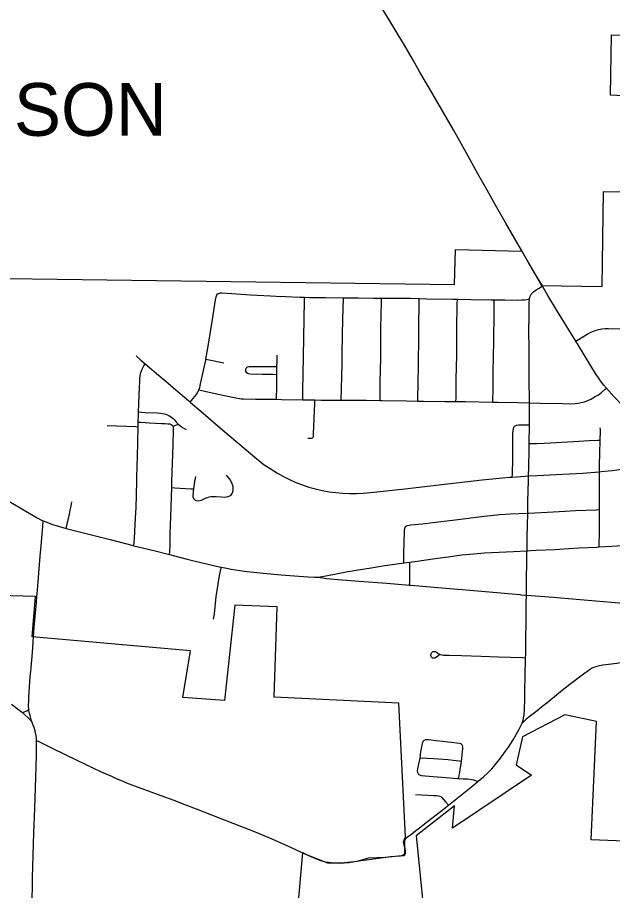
# Model space of a CAD drawing. Extents: x 1815539 to 1947826, y 273303 to 993194.
# Drawn here: x 1869978 to 1875617, y 925558 to 933838 of the extents above; entities that cross this region are included whole.
import ezdxf

# ---------------------------------------------------------------- set-up
doc = ezdxf.new("R2010")
doc.units = 0
for name, color, linetype in [('GM_X_City_Street', 7, 'Continuous'), ('GM_X_Corporation', 7, 'Continuous'), ('GM_X_Corporation_Text', 7, 'Continuous'), ('GM_X_County_Road', 7, 'Continuous'), ('GM_X_State_Route', 7, 'Continuous'), ('GM_X_Township_Road', 7, 'Continuous')]:
    doc.layers.add(name, color=color, linetype=linetype)

msp = doc.modelspace()

# ---------------------------------------------------------------- linework, layer by layer
at = {"layer": 'GM_X_City_Street'}
for points in [[(1874829, 931170.4), (1874832.1, 931185.5), (1874838, 931199.5), (1874846.5, 931212.7), (1874856.7, 931224.6), (1874868.3, 931235.4), (1874893.7, 931255.1), (1874920.8, 931272.3), (1874951.7, 931292)], [(1875268.5, 930769.3), (1875243.4, 930810.5), (1875096.9, 931048.5), (1875003.8, 931203.1), (1874953.7, 931288.6), (1874951.7, 931292)], [(1871763.6, 930597.2), (1871782.7, 930701.2), (1871825.7, 930973.5), (1871855.1, 931161.2), (1871860.9, 931189.5), (1871863.5, 931197.1), (1871868.1, 931207.8), (1871873.8, 931216.9)], [(1871873.8, 931216.9), (1871883.5, 931221.8), (1871891.7, 931224.8), (1871903.1, 931226.6), (1871915.8, 931226.3), (1871965.5, 931224.1), (1872184.9, 931209.3), (1872374.5, 931197.1), (1872430.9, 931193.7), (1872518.8, 931190.8), (1872655.1, 931186.4), (1872698.3, 931185.3)], [(1872681.8, 930213.3), (1872682, 930232.4), (1872682.7, 930308.9), (1872684.2, 930451.6), (1872697.6, 931150.5), (1872698.3, 931185.3)], [(1872698.3, 931185.3), (1872745, 931184.1), (1872898.3, 931181.7), (1873067.2, 931178.4)], [(1873045.4, 930208.6), (1873048.7, 930318.4), (1873053.4, 930546.7), (1873054.8, 930644.7), (1873059.3, 930829.7), (1873062.2, 930973.8), (1873067.2, 931178.4)], [(1873067.2, 931178.4), (1873207, 931178.5), (1873351.1, 931177), (1873427.8, 931176.4)], [(1873414.1, 930206.3), (1873414.4, 930230.8), (1873415.5, 930329.2), (1873416.5, 930395), (1873417.8, 930477.2), (1873420, 930624.9), (1873421.3, 930723.5), (1873422.3, 930871.6), (1873424.9, 931035.8), (1873427.3, 931117.9), (1873427.7, 931165.5), (1873427.8, 931176.4)], [(1873427.8, 931176.4), (1873503.4, 931175.6), (1873702.3, 931174.9), (1873785.5, 931173)], [(1873773.1, 930200.7), (1873773.3, 930219.9), (1873774.8, 930371.2), (1873777, 930533.7), (1873778.4, 930632.9), (1873779.9, 930728), (1873781.4, 930851.3), (1873782.1, 930972.7), (1873783.6, 931060.8), (1873785, 931146.2), (1873785.5, 931173)], [(1873785.5, 931173), (1873857.3, 931171.4), (1874103.6, 931166.4), (1874146.4, 931165.9)], [(1874133.2, 930195.9), (1874133.8, 930229.1), (1874136.4, 930392.3), (1874138.6, 930539.2), (1874140, 930620.8), (1874140.7, 930767.6), (1874141.2, 930881.9), (1874145.7, 931122.2), (1874146.4, 931165.9)], [(1874146.4, 931165.9), (1874276.6, 931164.2), (1874465.6, 931161.3), (1874496.8, 931160.9)], [(1874483.8, 930191.4), (1874483.9, 930218.4), (1874484.3, 930301.1), (1874487, 930416.8), (1874487.1, 930482.9), (1874488.9, 930615.1), (1874491.3, 930780.3), (1874491.9, 930846.3), (1874495.3, 930953.9), (1874496.2, 931044.8), (1874496.7, 931144.1), (1874496.8, 931160.9)], [(1874496.8, 931160.9), (1874597.2, 931159.8), (1874718.1, 931158.3), (1874757.8, 931159.1), (1874783.4, 931161.5), (1874805.1, 931164.8), (1874829, 931170.4)], [(1874829.6, 930184.1), (1874829.4, 930208.1), (1874828.9, 930257.2), (1874827.8, 930355.1), (1874827.4, 930432.6), (1874826.8, 930502), (1874826.2, 930583.6), (1874825.6, 930703.9), (1874825, 930860.9), (1874826.5, 931007.8), (1874826.9, 931138.3), (1874829, 931170.4)], [(1875268.5, 930769.3), (1875294, 930784.8), (1875336, 930810.4), (1875392.7, 930842.9), (1875421.8, 930857.1), (1875451.9, 930869), (1875483, 930878.3), (1875514.6, 930884.9), (1875546.6, 930888.1), (1875579.2, 930888.5), (1875710.2, 930884.3), (1875778.4, 930881.9)], [(1875559.9, 930322.9), (1875533.8, 930352.1), (1875503, 930391), (1875483.3, 930419.4), (1875461.6, 930453.1), (1875431.4, 930501.6), (1875328.7, 930670.1), (1875268.5, 930769.3)], [(1871101.6, 930629.6), (1871148.3, 930589.1), (1871189.5, 930553.2)], [(1872436.7, 930527.2), (1872437.4, 930570), (1872440.4, 930634.6)], [(1871125.7, 930097.1), (1871125.8, 930103.8), (1871128, 930171.6), (1871129.4, 930202.4), (1871130.5, 930230), (1871131.1, 930245.9), (1871131.2, 930259.4), (1871134.1, 930324.7), (1871136.6, 930390.4), (1871139, 930418.8), (1871141.2, 930438.7), (1871143.6, 930455.2), (1871147.6, 930471), (1871152.5, 930487.3), (1871158.2, 930502), (1871164.6, 930515.1), (1871175, 930533.3), (1871189.5, 930553.2)], [(1871189.5, 930553.2), (1871229.7, 930519.4), (1871295.7, 930462.9), (1871383.1, 930388.2), (1871478, 930307.1), (1871600.7, 930201.6), (1871615.3, 930189)], [(1871696.2, 930306), (1871704.9, 930328.7), (1871713.6, 930363.8), (1871762, 930588.1), (1871763.6, 930597.2)], [(1871763.6, 930597.2), (1871793.3, 930590.8), (1871932, 930561.4)], [(1872435.9, 930449.4), (1872396.4, 930451.5), (1872363.5, 930453.3), (1872297.4, 930453.8), (1872181.8, 930456.3), (1872165.5, 930459.2), (1872151.4, 930467.5), (1872143, 930481.3), (1872141.7, 930497.7), (1872146.4, 930513.7), (1872157.5, 930525.3), (1872173.4, 930529.3), (1872271, 930526.9), (1872403.2, 930527.1), (1872436.7, 930527.2)], [(1872435.9, 930449.4), (1872436, 930489.1), (1872436.7, 930527.2)], [(1872432, 930216.9), (1872433, 930246.5), (1872435.3, 930311.2), (1872435.9, 930449.4)], [(1871615.3, 930189), (1871640.9, 930222), (1871660.4, 930247.1), (1871683, 930279.9), (1871694.1, 930300.6), (1871696.2, 930306)], [(1871696.2, 930306), (1871726.4, 930299.6), (1871752.1, 930294.1), (1871881.4, 930266.4), (1872031.6, 930233.8), (1872096.3, 930222.6), (1872120.6, 930220.6), (1872233.2, 930218), (1872432, 930216.9)], [(1874829.6, 930184.1), (1874934.6, 930181.8), (1875148.4, 930176.9), (1875216.8, 930175.6), (1875263.6, 930176.4), (1875292.4, 930180.3), (1875320.8, 930185.6), (1875351.9, 930194.5), (1875382, 930205.9), (1875411.2, 930219.5), (1875453.1, 930242.1), (1875483.5, 930260.5), (1875512.4, 930281.4), (1875544.3, 930309.3), (1875559.9, 930322.9)], [(1875898.3, 929941.1), (1875888.8, 929955), (1875873.9, 929973.2), (1875852.7, 929998.3), (1875820.1, 930035.2), (1875710.5, 930157.2), (1875632.4, 930241.6), (1875559.9, 930322.9)], [(1872432, 930216.9), (1872479.5, 930216.7), (1872681.8, 930213.3)], [(1872681.8, 930213.3), (1872709.4, 930212.8), (1872796.8, 930210.9)], [(1872730.1, 929849.5), (1872765.1, 929849.3), (1872772.5, 929850.6), (1872778, 929854), (1872780.8, 929859.3), (1872782.9, 929865.7), (1872783.8, 929872), (1872784.5, 929887.5), (1872786.6, 929966.1), (1872792.2, 930099.9), (1872795.6, 930181.9), (1872796.8, 930210.9)], [(1872796.8, 930210.9), (1872857.2, 930209.5), (1873045.4, 930208.6)], [(1873045.4, 930208.6), (1873139.8, 930209.3), (1873287, 930208.1), (1873414.1, 930206.3)], [(1871615.3, 930189), (1871619, 930185.9), (1871714.6, 930103.8), (1871902.5, 929944.4), (1872064.7, 929805.8), (1872265.7, 929637), (1872317.3, 929597), (1872371.2, 929559.9), (1872440.8, 929517), (1872498.2, 929485.4), (1872556.7, 929456.1), (1872616.5, 929429.4), (1872677.5, 929405.7), (1872739.5, 929385), (1872802.4, 929366.9), (1872866.1, 929351.8), (1872930.4, 929340.1), (1872995.3, 929331.7), (1873060.6, 929326.1), (1873125.9, 929323.2), (1873190.9, 929323.3), (1873256, 929326.4), (1873353.7, 929335.4), (1873647.5, 929367.3), (1874136.7, 929423.6), (1874381.3, 929452.9), (1874511.9, 929466.9), (1874643, 929477.6), (1874667.1, 929479.3)], [(1873414.1, 930206.3), (1873434.2, 930206.1), (1873663.1, 930203), (1873773.1, 930200.7)], [(1873773.1, 930200.7), (1873826.7, 930199.6), (1874027.1, 930197.1), (1874133.2, 930195.9)], [(1874133.2, 930195.9), (1874219.3, 930195), (1874483.8, 930191.4)], [(1874483.8, 930191.4), (1874528.9, 930190.8), (1874718.7, 930186.5), (1874829.6, 930184.1)], [(1874829.6, 929973.9), (1874830.4, 930077.6), (1874829.6, 930184.1)], [(1871122.9, 930000.1), (1871124.9, 930070.3), (1871125.7, 930097.1)], [(1871125.7, 930097.1), (1871154.5, 930095.4), (1871187.1, 930093.5), (1871301.9, 930088.4), (1871334.5, 930085.2), (1871366.9, 930079.2), (1871382.7, 930075), (1871398, 930069.1), (1871412.9, 930062.2), (1871427, 930053.8), (1871440.3, 930044.1), (1871452.9, 930033.6), (1871464.6, 930022.2), (1871485.3, 929996.8), (1871496.7, 929985), (1871503.8, 929978.7)], [(1870828.7, 929967.4), (1871097.5, 929957.7), (1871121.7, 929956.8)], [(1871121.7, 929956.8), (1871122.9, 930000.1)], [(1871122.9, 930000.1), (1871148.5, 929998.7), (1871228.7, 929994.1), (1871343.8, 929988.4), (1871376.1, 929987.1), (1871403.4, 929985.2), (1871422.2, 929982.9), (1871433.8, 929979), (1871444.9, 929973.3), (1871458, 929963.7)], [(1871440.4, 929380.4), (1871442, 929432.1), (1871444.4, 929529.9), (1871449.8, 929692.7), (1871452.2, 929790.3), (1871456.4, 929925.1), (1871458, 929963.7)], [(1871458, 929963.7), (1871486.3, 929973.5), (1871503.8, 929978.7)], [(1871503.8, 929978.7), (1871509, 929974.1), (1871524.8, 929961.8), (1871543.2, 929949.1), (1871562.9, 929937.2), (1871577.8, 929929.5)], [(1874667.1, 929479.3), (1874667.7, 929507.2), (1874671.2, 929655.9), (1874671.1, 929753.9), (1874671.7, 929886.6), (1874674, 929919.8), (1874677.1, 929936.1), (1874682.5, 929951.8), (1874693.3, 929964.2), (1874708.2, 929971.1), (1874724.6, 929974.2), (1874741.2, 929975), (1874774.5, 929975.2), (1874829.6, 929973.9)], [(1874828.1, 929796.8), (1874829.6, 929973.9)], [(1871081.7, 928828.8), (1871084.4, 928865), (1871086.8, 928897.5), (1871090.8, 928962.7), (1871097.5, 929092.9), (1871099.5, 929141.8), (1871101.4, 929190.6), (1871105.5, 929303.4), (1871106, 929335.2), (1871106.7, 929351.3), (1871108.1, 929399), (1871108.9, 929431.6), (1871109.3, 929449.8), (1871109.9, 929473.2), (1871110.7, 929503.6), (1871111.9, 929555), (1871116.5, 929714.1), (1871117.6, 929770.2), (1871118.5, 929811), (1871119.5, 929863.1), (1871120.3, 929903), (1871120.7, 929923.5), (1871121.7, 929956.8)], [(1875500, 929830.8), (1875502.7, 929914.1), (1875502.4, 929930.4), (1875500.8, 929946.8)], [(1874821.4, 929489.8), (1874823.5, 929575.5), (1874827.5, 929739), (1874828.1, 929796.8)], [(1874828.1, 929796.8), (1874853.3, 929797.3), (1874902.6, 929798.3), (1874968.1, 929801.7), (1875033.5, 929805), (1875131.9, 929809.2), (1875246.7, 929816.1), (1875394.4, 929824.9), (1875476, 929829.5), (1875500, 929830.8)], [(1875494.8, 929529.6), (1875494.6, 929586.3), (1875496.8, 929717.3), (1875499.5, 929815.6), (1875500, 929830.8)], [(1875494.8, 929529.6), (1875509.6, 929530.9), (1875574.3, 929537.9), (1875615.7, 929543.3), (1875659.1, 929549.3), (1875742.5, 929561.5), (1875849.6, 929577.5), (1876028.5, 929599.5), (1876058, 929603.1)], [(1871646.8, 929366.5), (1871639.8, 929307.8), (1871641, 929291.5), (1871647.1, 929276.4), (1871657.9, 929264.3), (1871672.4, 929257.1), (1871688.5, 929255.1), (1871704.9, 929256.8), (1871720.8, 929261), (1871736, 929267.1), (1871765.1, 929281.9), (1871780.2, 929287.2), (1871796, 929291.6), (1871812, 929294.6), (1871828.2, 929296.2), (1871844.6, 929296.7), (1871861, 929296), (1871909.8, 929291.5), (1871942.5, 929289.4), (1871958.9, 929290.6), (1871974.6, 929294.5), (1871989.1, 929301.8), (1872001.5, 929312.2), (1872011.3, 929325.3), (1872018.3, 929340.2), (1872022.3, 929356), (1872023.3, 929372.3), (1872021.3, 929388.6), (1872017.1, 929404.4), (1872011.2, 929419.7), (1872004.2, 929434.4), (1871996.2, 929448.7), (1871987, 929462.2), (1871957.5, 929499)], [(1871664.8, 929485.4), (1871655.8, 929437.1), (1871649.5, 929389.3), (1871646.8, 929366.5)], [(1874667.1, 929479.3), (1874787.6, 929487.6), (1874821.4, 929489.8)], [(1874812.7, 929138.2), (1874814.5, 929232.2), (1874818.2, 929362.9), (1874820, 929428.3), (1874821.4, 929489.8)], [(1874821.4, 929489.8), (1874904.1, 929495.6), (1875084.3, 929504.2), (1875211.1, 929511.2), (1875335.3, 929518), (1875411.7, 929522.3), (1875494.8, 929529.6)], [(1875493.4, 929171.8), (1875494.3, 929323.8), (1875494.9, 929455.1), (1875494.8, 929529.6)], [(1871419.3, 928744.5), (1871420.6, 928770), (1871423.8, 928834), (1871425.8, 928943.2), (1871431.9, 929106.2), (1871440.4, 929380.4)], [(1871440.4, 929380.4), (1871468.3, 929378.3), (1871519.8, 929374.4), (1871623.1, 929368), (1871646.8, 929366.5)], [(1870440.9, 928992.5), (1870446.9, 929019.7), (1870470.9, 929126.9), (1870479, 929165.4), (1870486.8, 929204.4), (1870492.9, 929243.4)], [(1873655.7, 929010.9), (1873664.2, 929017.5), (1873672.4, 929021.3), (1873688.8, 929024.6), (1873705.8, 929026.1), (1873816.2, 929037.1), (1873913.5, 929048.5), (1874124.8, 929073.2), (1874401, 929107.3), (1874547.4, 929123.5), (1874645.3, 929130.6), (1874812.7, 929138.2)], [(1874806.6, 928780.7), (1874808.3, 928906.2), (1874812.7, 929138.2)], [(1874812.7, 929138.2), (1874825.1, 929138.5), (1875053.9, 929150.6), (1875168.4, 929156.5), (1875266.4, 929161.7), (1875462.3, 929170.4), (1875493.4, 929171.8)], [(1875491.2, 928817.1), (1875491.5, 928851.4), (1875491.7, 928878.3), (1875491.9, 928912.2), (1875492.1, 928942.5), (1875492.7, 929041.5), (1875493.5, 929144), (1875493.4, 929171.8)], [(1870163, 928351.1), (1870164.5, 928371.7), (1870174.4, 928485.2), (1870193, 928728.9), (1870202, 928827.7), (1870211.5, 928938.9), (1870217.7, 929011.7), (1870221.9, 929063.9)], [(1873640.8, 928664.7), (1873640.6, 928694.5), (1873640.4, 928742.8), (1873641.6, 928871.8), (1873644.2, 928961.1), (1873645.2, 928969), (1873646.1, 928981.1), (1873647.5, 928991.1), (1873650.6, 929001.3), (1873655.7, 929010.9)], [(1874800.2, 928360), (1874801.3, 928452), (1874802.5, 928550.1), (1874803.8, 928635.5), (1874806.1, 928756.3), (1874806.6, 928780.7)], [(1873693.1, 928455.9), (1873695.4, 928483.5), (1873696.7, 928499), (1873696.6, 928545.7), (1873696.5, 928639.2), (1873696.5, 928672.6)], [(1871837.2, 928133), (1871844.2, 928182), (1871862.5, 928345.8), (1871873, 928427.4), (1871886.5, 928508.7), (1871900.4, 928575.6), (1871908.3, 928614.6), (1871910.4, 928625.1)], [(1874792.8, 927766), (1874793.8, 927796.7), (1874795.3, 927944.3), (1874797.2, 928108.1), (1874798.4, 928196.7), (1874799.2, 928281.7), (1874800.2, 928360)], [(1873981.2, 927795.9), (1873957, 927776.8), (1873943.8, 927768.3), (1873933.7, 927763.3), (1873923.9, 927761.7), (1873915.5, 927763.1), (1873908.8, 927766), (1873902.5, 927771.7), (1873898.2, 927778), (1873896.1, 927785.9), (1873895.5, 927793.8), (1873897, 927802.1), (1873899.9, 927809.4), (1873905.6, 927816.5), (1873911.3, 927820.9), (1873918.7, 927824.2), (1873926.6, 927825.2), (1873936, 927824.2), (1873942.3, 927821.2), (1873949.9, 927817.6), (1873956.6, 927813.1), (1873969.9, 927803.8), (1873984.6, 927796.8), (1873999.4, 927793.3), (1874015.1, 927791.5), (1874068.2, 927789.4), (1874184.1, 927786.5), (1874373.5, 927781.4), (1874536.2, 927774.9), (1874764.3, 927767), (1874792.8, 927766)], [(1874782.6, 927269.5), (1874783.9, 927309.6), (1874785.1, 927338.1), (1874787.3, 927465.6), (1874788.3, 927583.9), (1874792.8, 927766)], [(1874901.3, 927266.1), (1874943.3, 927299.4), (1874960.1, 927312.9), (1874981.5, 927330.1), (1875008.8, 927352.1), (1875035.1, 927373.1), (1875047.7, 927383.3), (1875123.9, 927444.5), (1875213.7, 927514.2), (1875343.1, 927614.1), (1875382.3, 927642.9), (1875398.9, 927654.5), (1875418.9, 927666.7), (1875438.2, 927675.1), (1875452.9, 927681), (1875471, 927686.7), (1875493.6, 927692.7), (1875523.9, 927697.9), (1875606.7, 927708.8), (1875677.1, 927718.1), (1875741.8, 927725.5), (1875823.1, 927733.8)], [(1874761.8, 927145.5), (1874769.1, 927173.2), (1874774.3, 927196.8), (1874779.1, 927229), (1874782.6, 927269.5)], [(1874761.8, 927145.5), (1874788, 927174.8), (1874806.5, 927192), (1874825.1, 927206.5), (1874852, 927227.6), (1874877.9, 927247.8), (1874901.3, 927266.1)], [(1874339, 926592.6), (1874365.4, 926612.9), (1874390.3, 926634), (1874437.9, 926678.7), (1874472, 926713.8), (1874504.2, 926750.5), (1874555.3, 926813.8), (1874603.8, 926879.1), (1874631.1, 926919.5), (1874674.1, 926988.6), (1874730.6, 927087.2), (1874761.8, 927145.5)], [(1874184.7, 926783.9), (1874187.9, 926806.2), (1874196.5, 926884.4), (1874197.8, 926895.3), (1874198.5, 926910.6), (1874198.5, 926917.5), (1874197.9, 926922.4), (1874196.7, 926927.5), (1874195.5, 926932.6), (1874193.3, 926937), (1874190.4, 926941.8), (1874186.4, 926946.1), (1874180.1, 926949.4), (1874167.9, 926952.9), (1874139, 926957.3), (1874089.9, 926962.5), (1874057.2, 926965.7), (1874008.5, 926972), (1873943.1, 926979.2), (1873877.6, 926986.9), (1873861.1, 926988), (1873844.7, 926986.6), (1873829.7, 926980.5), (1873823.3, 926976.3), (1873818.4, 926968.9), (1873811.8, 926954.1), (1873805.1, 926921.8), (1873797.3, 926873), (1873789.4, 926813.9)], [(1873789.4, 926813.9), (1873774.5, 926743.6), (1873768.4, 926711), (1873766.6, 926694.5), (1873767.9, 926678.2), (1873770.7, 926670.5), (1873775, 926663.7), (1873781, 926657.6), (1873787.6, 926654), (1873794.6, 926651.9), (1873803.7, 926650.3), (1873918.6, 926640.1), (1874000.5, 926632.4), (1874148.3, 926620.9), (1874161.5, 926620.4)], [(1873789.4, 926813.9), (1873816.3, 926815.6), (1873857.3, 926814.6), (1873922.7, 926810.4), (1874011.7, 926805.2), (1874058.6, 926800.9), (1874105.4, 926795.7), (1874136.7, 926791.4), (1874162.8, 926787), (1874184.7, 926783.9)], [(1874161.5, 926620.4), (1874165.1, 926652.3), (1874168.7, 926678.7), (1874173.2, 926710.6), (1874178.4, 926741), (1874184.7, 926783.9)], [(1874061.6, 926366.9), (1874157.2, 926443.5), (1874283.4, 926544.7), (1874339, 926592.6)], [(1874161.5, 926620.4), (1874200.9, 926618.7), (1874244.4, 926616.9), (1874280, 926612.5), (1874298.2, 926608.2), (1874318.2, 926602.1), (1874339, 926592.6)], [(1873750.2, 926470.2), (1873923.1, 926460.6), (1873949.2, 926459.3), (1873968.4, 926456.9), (1873979.1, 926454.2), (1873989.2, 926448.6), (1873999.9, 926439.8), (1874015.2, 926421.8), (1874034.6, 926399.1), (1874061.6, 926366.9)], [(1873664.4, 926059.5), (1873672.3, 926065.7), (1873682, 926072.9), (1873702, 926087.8), (1873730.9, 926109.4), (1873748.7, 926123.7)]]:
    msp.add_lwpolyline(points, dxfattribs=at)
at = {"layer": 'GM_X_Corporation'}
for points in [[(1869884.7, 931364.1), (1874120.7, 931306.2), (1874128.1, 931638.6), (1874758.5, 931622.9), (1874943.3, 931295), (1875517.5, 931287.1), (1875529.7, 932187.2), (1876894.7, 932168.6), (1876882.5, 931268.4), (1877159.8, 931264.6), (1877561.1, 933143.1), (1876694.2, 933188.4), (1876694.2, 933045.4), (1875596.5, 933102.8), (1875606.4, 933672.8), (1878174.1, 933595.7), (1878209.7, 933819.2), (1878222, 933909.5)], [(1872581.5, 924769.4), (1872681.5, 925919.6), (1872724.2, 925898.3), (1872917.3, 925820.3), (1873049.2, 925821.2), (1873197.8, 925837.9), (1873307.4, 925867.6), (1873461.5, 925875.1), (1873619.4, 925891.8), (1873647.2, 925904.8), (1873649.1, 925962.4), (1873636.1, 926020), (1873652.8, 926062.7), (1873656.6, 926065.4), (1873591.6, 927335.9), (1872410, 927393.7), (1872437.4, 928250.3), (1872037.4, 928263.2), (1871940.1, 927361.5), (1871546.1, 927390.1), (1871617.3, 927831.5), (1870116, 927964.7), (1870149.9, 928348.2), (1868739.7, 928385.9)], [(1876482.9, 925000), (1876684.6, 925989.2), (1875415.8, 926039.1), (1875466.1, 927160.4), (1875163.7, 927224.7), (1874764.8, 927017.2), (1874702.9, 926751.3), (1874848.7, 926652.6), (1874101.6, 926150.7), (1874120.5, 926361.8), (1873756.8, 926075.9), (1873891.8, 924723.2)]]:
    msp.add_lwpolyline(points, dxfattribs=at)
at = {"layer": 'GM_X_County_Road'}
for points in [[(1874757.4, 931624.3), (1874686.8, 931745), (1874605.3, 931886.9), (1874506.7, 932057), (1874411.6, 932229), (1874341.4, 932355.5), (1874228.8, 932558.1), (1874108.7, 932772), (1873883.4, 933164.5), (1873792.3, 933320), (1873726.7, 933433.1), (1873644.1, 933574.2), (1873585.7, 933672.8), (1873510.6, 933799.7), (1873384, 934010.2)], [(1874951.7, 931292), (1874903, 931375.2), (1874878.2, 931417.6), (1874821.8, 931514), (1874757.4, 931624.3)]]:
    msp.add_lwpolyline(points, dxfattribs=at)
at = {"layer": 'GM_X_State_Route'}
for points in [[(1869896.8, 929250.5), (1870165.6, 929093), (1870199.5, 929074.7), (1870221.9, 929063.9), (1870255, 929050.5), (1870301.5, 929033.7), (1870376.1, 929011.6), (1870440.9, 928992.5), (1870490.7, 928978.6), (1870856.6, 928887.4), (1871062.8, 928833.4), (1871081.7, 928828.8), (1871269.8, 928782.8), (1871419.3, 928744.5), (1871454.4, 928735.5), (1871587.4, 928701.5), (1871714.4, 928670), (1871906.1, 928626.1), (1871910.4, 928625.1), (1871957.7, 928614.7), (1872002.6, 928606.4), (1872083.8, 928593.9), (1872151.3, 928584.4), (1872217.3, 928577.5), (1872306.7, 928567.9), (1872478.3, 928552.2), (1872643.6, 928539.3), (1872733, 928534.1), (1872793.5, 928531.2), (1872831.7, 928530.8)], [(1874838.5, 928782.3), (1874892.9, 928785.2), (1875073.2, 928793.9), (1875204.2, 928801.1), (1875301.8, 928807.1), (1875463.7, 928815.5), (1875491.2, 928817.1), (1875610.8, 928823.9), (1875758.2, 928832.6), (1876081.3, 928854)], [(1872831.7, 928530.8), (1872915.2, 928546), (1872998.4, 928562.9), (1873094.2, 928579.3), (1873207.7, 928598.9), (1873311.8, 928616.8), (1873441.4, 928636.7), (1873640.8, 928664.7), (1873696.5, 928672.6), (1873766.8, 928682.5), (1873913.4, 928702.7), (1874059.4, 928724.2), (1874189.3, 928741.3), (1874303.3, 928753), (1874401, 928760.4), (1874679.6, 928774.4), (1874806.6, 928780.7), (1874838.5, 928782.3)], [(1872831.7, 928530.8), (1872868.5, 928523.7), (1872908, 928517.6), (1873055, 928506.2), (1873216.3, 928493.5), (1873478.5, 928473.2), (1873693.1, 928455.9), (1873707.9, 928454.5), (1874035, 928427), (1874231.4, 928409.7), (1874411.5, 928393.6), (1874738.9, 928364.7), (1874747.4, 928364.1)], [(1874747.4, 928364.1), (1874800.2, 928360), (1875017.4, 928342.4), (1875309.9, 928318.8)], [(1875309.9, 928318.8), (1875311.7, 928318.6), (1875458.9, 928306.6), (1875602.6, 928293.1), (1875720, 928282.1), (1875882.9, 928266.6), (1875903.1, 928264.7), (1875980.9, 928257.1), (1876160.4, 928237.4), (1876242, 928226.7), (1876281.1, 928220.1)]]:
    msp.add_lwpolyline(points, dxfattribs=at)
at = {"layer": 'GM_X_Township_Road'}
for points in [[(1870129.9, 927965.6), (1870137.1, 928057.3), (1870151, 928222), (1870157, 928287.8), (1870163, 928351.1)], [(1870085.9, 927274.9), (1870084.9, 927282.9), (1870083.6, 927303.7), (1870084.2, 927364.8), (1870085.5, 927393.3), (1870088.7, 927440.2), (1870092, 927489.7), (1870095, 927535.8), (1870099.6, 927587.1), (1870103.8, 927635), (1870119.7, 927817.1), (1870129.9, 927965.6)], [(1869921.1, 927326.2), (1869999.9, 927267), (1870026.3, 927245.8)], [(1870026.3, 927245.8), (1870045.5, 927252.8), (1870057.3, 927258.5), (1870066.1, 927263.5), (1870080.8, 927272), (1870085.9, 927274.9)], [(1870026.3, 927245.8), (1870037.6, 927235.4), (1870086.4, 927189.5), (1870111.5, 927163.4)], [(1870111.5, 927163.4), (1870103.1, 927198.1), (1870098.1, 927217.5), (1870093.1, 927236.1), (1870087.1, 927264.6), (1870085.9, 927274.9)], [(1870159.1, 926981.4), (1870157.4, 927008.4), (1870152.7, 927041.3), (1870145.3, 927073.6), (1870135.5, 927105.3), (1870124.7, 927134.2), (1870115.9, 927154.9), (1870111.5, 927163.4)], [(1870115.1, 925417.2), (1870119.7, 925581.2), (1870121.7, 925679.6), (1870128, 925892.7), (1870134.6, 926105.9), (1870142.4, 926335.4), (1870151.5, 926630.6), (1870157.9, 926843.8), (1870159.5, 926975.3), (1870159.1, 926981.4)], [(1870159.1, 926981.4), (1870180.7, 926971.4), (1870211.1, 926957.3), (1870313.8, 926905.8), (1870535.5, 926799), (1870772, 926685.3), (1870868.7, 926641.5), (1870906.6, 926624.3), (1870978, 926594), (1871012.3, 926579.4), (1871088.6, 926549.7), (1871335.4, 926460.5), (1871458.4, 926415), (1871581, 926368.6), (1871672.5, 926332.6), (1871890.3, 926246.7), (1872018.8, 926196.4), (1872133.4, 926153), (1872230.7, 926113.9), (1872329.7, 926073.1), (1872388.3, 926047.8), (1872538.1, 925981.5), (1872612.7, 925947.7), (1872683.9, 925913.4)], [(1873748.7, 926123.7), (1873786.8, 926153), (1873864.2, 926212.6), (1874016.1, 926330.9), (1874061.6, 926366.9)], [(1872751.3, 925883), (1872756.7, 925880.5), (1872817, 925855.5), (1872863.5, 925840), (1872895.1, 925832), (1872927.3, 925826), (1872975.9, 925820.6), (1873024.9, 925818.8), (1873073.8, 925820.6), (1873122.2, 925825.5), (1873155.3, 925830.9), (1873171.4, 925833.5), (1873231, 925842.2), (1873285.4, 925850.2), (1873331.5, 925856.9), (1873374.1, 925863.2), (1873418.4, 925868.4), (1873467.9, 925874.5), (1873513.9, 925879.7), (1873558.3, 925883), (1873606.8, 925886.6), (1873633.3, 925889), (1873640.6, 925891.8), (1873647.9, 925896.4), (1873653.3, 925902.1), (1873655.4, 925909.8), (1873654.4, 925925.1), (1873650.5, 925957.5), (1873648.9, 925973.7), (1873647.4, 926005.9), (1873647.7, 926022), (1873649.2, 926034.2), (1873652.2, 926043.1), (1873657.1, 926051.4), (1873660.1, 926055.5), (1873664.4, 926059.5)], [(1872683.9, 925913.4), (1872751.3, 925883)]]:
    msp.add_lwpolyline(points, dxfattribs=at)

# ---------------------------------------------------------------- texts
at = {"layer": 'GM_X_Corporation_Text'}
msp.add_text('EDISON', height=500, rotation=0.00001, dxfattribs=at).set_placement((1868830.1, 932716.2))

doc.saveas('drawing.dxf')
